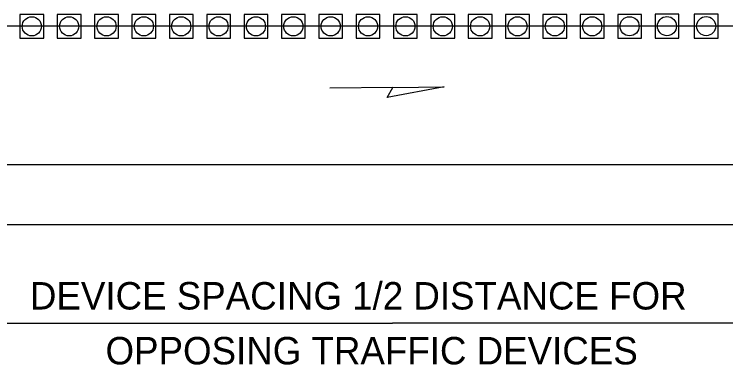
# Model space of a CAD drawing. Extents: x 99988 to 100172, y 99995 to 100047.
# Drawn here: x 100007.282 to 100009.097, y 100004.257 to 100005.151 of the extents above; entities that cross this region are included whole.
import ezdxf

# ---------------------------------------------------------------- set-up
doc = ezdxf.new("R2010")
doc.units = 0
for name, color, linetype in [('Default', 7, 'Continuous'), ('Level 15', 7, 'Continuous'), ('Level 20', 7, 'Continuous'), ('SH_GI_TrafficMvmntArrowRt1Lane', 7, 'Continuous'), ('TR_WZ_TrafficSafetyCone', 7, 'Continuous'), ('TR_WZ_WorkZoneDetails', 7, 'Continuous')]:
    doc.layers.add(name, color=color, linetype=linetype)

msp = doc.modelspace()

# ---------------------------------------------------------------- linework, layer by layer
at = {"layer": 'Default'}
msp.add_line((100012.5819, 100005.1207), (100002.4254, 100005.1207), dxfattribs=at)
at = {"layer": 'Level 15'}
for p in [(100007.041, 100004.3634), (100009.4533, 100004.3634)]:
    msp.add_line(p, (100008.2472, 100004.3634), dxfattribs=at)
at = {"layer": 'SH_GI_TrafficMvmntArrowRt1Lane'}
msp.add_line((100008.2478, 100004.965), (100008.0871, 100004.9629), dxfattribs=at)
msp.add_lwpolyline([(100008.3788, 100004.9667), (100008.2333, 100004.9391), (100008.2478, 100004.965)], close=True, dxfattribs=at)
at = {"layer": 'TR_WZ_TrafficSafetyCone'}
for points in [[(100007.2965, 100005.0904), (100007.3572, 100005.0904), (100007.3572, 100005.1511), (100007.2965, 100005.1511)], [(100007.3918, 100005.0904), (100007.4525, 100005.0904), (100007.4525, 100005.1511), (100007.3918, 100005.1511)], [(100007.4871, 100005.0904), (100007.5478, 100005.0904), (100007.5478, 100005.1511), (100007.4871, 100005.1511)], [(100007.5824, 100005.0904), (100007.6431, 100005.0904), (100007.6431, 100005.1511), (100007.5824, 100005.1511)], [(100007.6777, 100005.0904), (100007.7384, 100005.0904), (100007.7384, 100005.1511), (100007.6777, 100005.1511)], [(100007.773, 100005.0904), (100007.8337, 100005.0904), (100007.8337, 100005.1511), (100007.773, 100005.1511)], [(100007.8682, 100005.0904), (100007.929, 100005.0904), (100007.929, 100005.1511), (100007.8682, 100005.1511)], [(100007.9635, 100005.0904), (100008.0243, 100005.0904), (100008.0243, 100005.1511), (100007.9635, 100005.1511)], [(100008.0588, 100005.0904), (100008.1196, 100005.0904), (100008.1196, 100005.1511), (100008.0588, 100005.1511)], [(100008.1541, 100005.0904), (100008.2148, 100005.0904), (100008.2148, 100005.1511), (100008.1541, 100005.1511)], [(100008.2494, 100005.0904), (100008.3101, 100005.0904), (100008.3101, 100005.1511), (100008.2494, 100005.1511)], [(100008.3447, 100005.0904), (100008.4054, 100005.0904), (100008.4054, 100005.1511), (100008.3447, 100005.1511)], [(100008.44, 100005.0904), (100008.5007, 100005.0904), (100008.5007, 100005.1511), (100008.44, 100005.1511)], [(100008.5353, 100005.0904), (100008.596, 100005.0904), (100008.596, 100005.1511), (100008.5353, 100005.1511)], [(100008.6306, 100005.0904), (100008.6913, 100005.0904), (100008.6913, 100005.1511), (100008.6306, 100005.1511)], [(100008.7258, 100005.0904), (100008.7866, 100005.0904), (100008.7866, 100005.1511), (100008.7258, 100005.1511)], [(100008.8211, 100005.0905), (100008.8819, 100005.0905), (100008.8819, 100005.1512), (100008.8211, 100005.1512)], [(100008.9164, 100005.0908), (100008.9772, 100005.0908), (100008.9772, 100005.1515), (100008.9164, 100005.1515)], [(100009.0164, 100005.0908), (100009.0772, 100005.0908), (100009.0772, 100005.1515), (100009.0164, 100005.1515)]]:
    msp.add_lwpolyline(points, close=True, dxfattribs=at)
for centre in [(100007.3269, 100005.1207), (100007.4222, 100005.1207), (100007.5175, 100005.1207), (100007.6127, 100005.1207), (100007.708, 100005.1207), (100007.8033, 100005.1207), (100007.8986, 100005.1207), (100007.9939, 100005.1207), (100008.0892, 100005.1207), (100008.1845, 100005.1207), (100008.2798, 100005.1207), (100008.3751, 100005.1207), (100008.4703, 100005.1207), (100008.5656, 100005.1207), (100008.6609, 100005.1207), (100008.7562, 100005.1207), (100008.8515, 100005.1208), (100008.9468, 100005.1211), (100009.0468, 100005.1211)]:
    msp.add_circle(centre, 0.0244, dxfattribs=at)
at = {"layer": 'TR_WZ_WorkZoneDetails'}
for p, q in [((100011.7483, 100004.7676), (100002.4278, 100004.7676)), ((100011.7483, 100004.6142), (100002.4307, 100004.6142))]:
    msp.add_line(p, q, dxfattribs=at)

# ---------------------------------------------------------------- texts
at = {"layer": 'Level 20'}
for s, p in [('DEVICE SPACING 1/2 DISTANCE FOR', (100007.3221, 100004.3984)), ('OPPOSING TRAFFIC DEVICES', (100007.5149, 100004.2584))]:
    msp.add_text(s, height=0.07, dxfattribs=at).set_placement(p)

doc.saveas('drawing.dxf')
